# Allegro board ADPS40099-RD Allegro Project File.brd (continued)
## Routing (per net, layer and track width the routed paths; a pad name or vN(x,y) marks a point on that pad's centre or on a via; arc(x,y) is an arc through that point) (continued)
UNNAMED_3_ADMAX77542_I31_SEL2: length 4.9
  BOTTOM w0.254: v3(90.1,19.59) 89.03,19.59 88.77,19.34 88.77,18.67 87.88,17.78 R48.1
UNNAMED_3_ADMAX77542_I31_SEL3: length 5
  BOTTOM w0.254: v3(90.1,20.79) 89.03,20.79 88.77,21.05 88.77,21.59 87.5,22.86 R50.1
UNNAMED_3_ADMAX77542_I31_SEL4: length 6.2
  BOTTOM w0.254: v3(90.5,20.79) 91.57,20.79 91.82,21.05 91.82,21.59 94.49,24.26 R55.1
UNNAMED_3_ADMAX77857_I197_BST1: length 2.7
  TOP w0.229: U3.A3 93.71,45.83 93.22,45.34 C17.2
UNNAMED_3_ADMAX77857_I197_BST2: length 2.7
  TOP w0.229: U3.E3 96.67,45.83 97.16,45.34 C21.1
UNNAMED_3_ADMAX77857_I197_EN1: length 10.2
  TOP w0.229: v3(94.72,45.83) U3.B2
  BOTTOM w0.203: P17.2 88.82,42.06 88.82,43 89.13,43.31 91.06,43.31 92.46,44.7 93.6,44.7 v3(94.72,45.83)
UNNAMED_3_ADMAX77857_I197_IN1: length 4.1
  TOP w0.229: U3.B4 U3.A4 U3.A5 U3.A6
  BOTTOM w0.508: R76.1 86.65,47.31 P35.1
UNNAMED_3_ADMAX77857_I197_LX11: length 11.6
  TOP w0.229: U3.B5 U3.B6 U3.B7 U3.A7 94.32,47.79 v1(93.98,48.13) 93.6,48.51 v1(93.34,48.51) v1(93.34,47.75)
  TOP w0.508: C17.1 v1(89.33,45.34)
  BOTTOM w0.508: v1(93.98,48.13) 93.98,45.97 93.34,45.34 v1(89.33,45.34)
  vias: v1(92.04,53.98) v1(92.04,52.71) v1(92.04,51.44) v1(92.93,53.98) v1(92.93,52.71) v1(92.93,51.44)
UNNAMED_3_ADMAX77857_I197_POKB: length 3.4
  BOTTOM w0.203: v3(95.12,45.43) 95.12,43.3 R27.2
UNNAMED_3_ADMAX77857_I197_SEL: length 3
  TOP w0.229: R77.1 96.69,43.27 95.52,44.43 U3.D1
UNNAMED_3_CN3P_I185_N1: length 2.5
  BOTTOM w0.508: R76.2 88.09,43.87 P17.1
UNNAMED_5_ADLTC3621V2_I158_FB: length 8.2
  TOP w0.203: v1(44.45,9.02) 44.74,9.31 U9.5
  BOTTOM w0.254: v1(44.45,9.02) 44.45,7.96 R92.1
  BOTTOM w0.305: C107.2 46.15,5.8 R102.2 45.81,5.46 R91.1 R92.1
UNNAMED_5_ADLTC3621V2_I158_INTVCC: length 11.6
  TOP w0.254: U9.6 v1(45.39,8.83)
  BOTTOM w0.254: R99.2 47.08,10.67 C106.1 46.39,9.18 46.05,8.83 v1(45.39,8.83)
  BOTTOM w0.381: R99.2 48.39,11.47 48.39,10.79 48.96,10.22 R100.1 51.39,10.22 51.68,10.52 P41.2
UNNAMED_5_ADLTC3621V2_I158_PGOOD: length 5.8
  TOP w0.203: U9.4 44.74,14.58 44.64,14.48 v1(44.06,14.48)
  BOTTOM w0.305: R99.1 48.13,14.1 47.75,14.48 v1(44.06,14.48)
UNNAMED_5_ADLTC3621V2_I158_RUN: length 11.5
  TOP w0.203: v1(44.07,15.88) 44.88,15.88 45.03,15.73 45.07,15.73 45.2,15.59 45.2,15.55 45.39,15.36 U9.3
  BOTTOM w0.381: P39.2 49.56,20.09 45.34,15.88 v1(44.07,15.88)
UNNAMED_5_ADMAX1722X_I186_EN: length 1.7
  TOP w0.356: U10.6 36.21,20.42 R103.2
UNNAMED_5_ADMAX1722X_I186_LX: length 5.1
  TOP w0.356: U10.2 35.56,24.64 35.05,25.15 33.27,25.15 32.77,24.64 L9.2
UNNAMED_5_ADMAX1722X_I186_SEL: length 1.9
  TOP w0.356: U10.4 v1(34.28,21.95)
  BOTTOM w0.356: R45.1 35.5,21.95 v1(34.28,21.95)
UNNAMED_5_ADMAX38889_I125_BKB: length 4.8
  TOP w0.254: U5.4 63.87,17.44 64.41,16.89 64.9,16.89 66.1,15.68 v1(66.1,15.2)
  BOTTOM w0.305: R95.1 v1(66.1,15.2)
UNNAMED_5_ADMAX38889_I125_CAP: length 9.2
  TOP w0.254: U5.2 62.87,17.8 v1(62.87,16)
  TOP w0.381: 69.09,10.88 C73.P 70.07,9.91
  BOTTOM w0.254: v1(66.17,16.89) 66.17,17.53 65.87,17.82 R51.1 63.54,17.82 62.87,17.14 v1(62.87,16)
UNNAMED_5_ADMAX38889_I125_FBCH: length 6.9
  TOP w0.254: v1(63.37,23.62) 63.37,23.62 U5.10
  BOTTOM w0.254: R53.1 v1(63.37,23.62)
  BOTTOM w0.508: R52.2 R53.1 62.35,22.57 C88.1
UNNAMED_5_ADMAX38889_I125_FBCR: length 6.7
  TOP w0.254: v1(66.29,21.84) 64.26,21.84 63.87,21.45 U5.9
  BOTTOM w0.254: R51.2 R52.1 65.83,20.87 66.29,21.34 v1(66.29,21.84)
UNNAMED_5_ADMAX38889_I125_FBS: length 5.6
  TOP w0.254: R71.2 62.61,23.46 62.61,22.1 62.87,21.84 U5.11
  TOP w0.305: R71.2 R72.1
UNNAMED_5_ADMAX38889_I125_ISET: length 2.3
  TOP w0.254: R57.1 61.68,22.14 62.37,21.45 U5.12
UNNAMED_5_ADMAX38889_I125_RDY: length 22.7
  TOP w0.254: U5.3 63.37,17.02 64.39,16
  TOP w0.305: RDY.1 60.33,8.64 60.96,9.27 60.96,12.95 60.41,13.5 v1(59.44,13.5) 59.44,13.97 60.07,14.61 64.01,14.61 64.39,14.99 64.39,16
  BOTTOM w0.305: R97.2 v1(59.44,13.5)
UNNAMED_5_CAP_I104_N1: length 7.5
  TOP w0.508: 57.79,19.05 57.79,17.14 58.88,16.05 v1(60.58,16.05)
  BOTTOM w0.254: R97.1 R96.1
  BOTTOM w0.305: R97.1 v1(60.58,16.05)
UNNAMED_5_CAP_I119_N1: length 3.1
  BOTTOM w0.381: BKB.1 66.04,3.58 ; BKB.1 65,2.54 ; BKB.1 67.08,2.54
UNNAMED_5_NC2P_I157_N1: length 1.4
  BOTTOM w0.305: P38.1 R92.2
UNNAMED_5_NC2P_I163_N1: length 17
  TOP w0.203: 46.23,9.27 46.05,9.45 U9.7
  TOP w0.305: v1(47.5,9.14) 46.36,9.14 46.23,9.27
  BOTTOM w0.305: v1(47.5,9.14) 52.58,9.14 53.21,9.78 53.21,11.48 52.81,11.89 P41.1 49.81,11.89 R100.2 R101.1 51.64,13.22 P42.2
UNNAMED_5_NC2P_I176_N1: length 1.4
  BOTTOM w0.305: R91.2 P28.1
UNNAMED_5_RES_I103_N2: length 1.7
  TOP w0.305: R69.2 54.61,25.78 R98.1
UNNAMED_6_CAP_I13_N2: length 4
  TOP w0.381: 18.8,13.84 18.8,15.14 18.45,15.48 C117.2 18.5,16.17 R117.1
UNNAMED_6_IC24XX32AV2_I1_A0: length 3.4
  TOP w0.305: U14.1 v1(17.53,7.29)
  BOTTOM w0.305: R111.2 17.53,6.69 v1(17.53,7.29) 17.53,7.91 R112.1
UNNAMED_6_IC24XX32AV2_I1_A1: length 3.2
  TOP w0.305: U14.2 v1(18.8,7.29)
  BOTTOM w0.305: R109.2 v1(18.8,7.29) R110.1
UNNAMED_6_IC24XX32AV2_I1_A2: length 3.4
  TOP w0.305: U14.3 v1(20.07,7.29)
  BOTTOM w0.305: R61.2 20.07,6.69 v1(20.07,7.29) 20.07,7.91 R62.1
UNNAMED_6_IC24XX32AV2_I1_SCL: length 2.2
  TOP w0.508: 20.07,13.84 R113.1
UNNAMED_6_IC24XX32AV2_I1_SDA: length 2.3
  TOP w0.508: 21.34,13.84 21.34,15.21 21.59,15.47 R114.1
VCIN: length 10.8
  TOP w0.254: C8.1 35.69,41.02 34.66,39.99 U2.A5
  TOP w0.381: P50.2 39.12,44.2 36.92,42 C8.1
VIO: length 12.2
  TOP w0.508: R4.1 v1(48.01,56.9) ; R13.2 v1(48.01,53.85) ; R3.1 v1(48.01,60.07) ; R14.2 v1(48.01,63.12)
  BOTTOM w0.381: C13.1 42.96,68.83 44.2,68.83 44.45,69.09 U7.5
  BOTTOM w0.508: R19.1 43.05,71.92 v1(43.05,70.99) ; v1(45.85,70.99) 45.85,71.92 R18.1 ; R9.2 v1(39.75,56.26) ; v1(42.08,70.99) C13.1 ; R10.2 v1(39.75,59.31)
VIO1: length 45.5
  TOP w0.254: U2.B1 32.04,38.73 31.72,39.04
  TOP w0.508: P22.2 46.36,40.89 47.37,41.91 47.37,44.83 46.23,45.97 32.41,45.97 v1(30.07,43.64) 30.07,43.63 30.07,42.67 R63.2 29.11,41.69 29.11,40.16 29.73,39.54 C5.1 31.23,39.54 31.72,39.04
  L3_SIG w0.508: v1(30.07,43.64) 34.51,43.64 v1(36.89,41.25)
  BOTTOM w0.508: R25.1 R58.1 36.35,41.79 v1(36.89,41.25)
VIO2: length 23
  TOP w0.254: U2.C1 32.08,38.23 31.78,37.92
  TOP w0.508: 31.78,37.92 30.26,36.41 C6.1 29.38,36.41 29.08,36.12 v1(29.08,33.76) 27.08,31.75 P23.2
  BOTTOM w0.635: v1(29.08,33.76) 29.08,34.42 30.01,35.34 R8.1 R5.1
VIO3: length 11.3
  TOP w0.229: U3.A2 94.1,45.43 92.71,44.04 C86.1
  TOP w0.508: v1(90.93,44.04) C86.1
  L3_SIG w0.381: 86.42,38.23 P17.3 ; P17.3 88.63,38.23 ; P17.3 87.53,39.33 ; P17.3 87.53,37.12
  BOTTOM w0.508: v1(92.84,40.64) R80.1 R27.1 ; R78.1 v1(91.06,40.64)
VIO4: length 37
  TOP w0.508: v1(75.22,60.36) 74.78,60.81 R34.2
  L3_SIG w1.016: v1(75.22,60.36) 77.98,57.61 77.98,54.1 75.22,51.35 75.22,41.82 72.82,39.42 65.48,39.42 P27.2
VIO6: length 80.1
  TOP w0.229: C75.1 86.96,20.39 U6.A6
  TOP w0.508: v1(79.25,19.43) 80.14,20.32 83.31,20.32 83.69,19.94 v1(83.69,19.3) R59.2 86.27,20.95 C75.1
  L4_PWR w0.508: v1(84.84,26.04) 84.84,20.45 v1(83.69,19.3) 85.26,17.74 v1(85.26,15.62) 85.26,12.53 87.38,10.41 93.98,10.41 95.63,12.07 v1(95.63,14.61) 95.63,15.32 97.16,16.84 97.16,21.59 95.63,23.11 v1(95.63,25.4)
  BOTTOM w0.254: R15.2 v1(95.63,14.61)
  BOTTOM w0.381: v1(95.63,25.4) 95,26.04 R85.2 ; R70.2 v1(84.84,26.04) ; R47.2 v1(85.26,15.62)
  BOTTOM w0.508: P29.2 65.79,25.27 66.42,24.64 66.42,22.99 70.48,18.92 78.74,18.92 v1(79.25,19.43) R60.2 ; R59.2 v1(83.69,19.3)
VIO8: length 56
  TOP w0.508: R22.1 R21.1 56.77,44.99
  TOP w0.635: 56.77,44.99 v1(56.77,44.2) 56.77,41.78 54.36,39.37 54.36,37.59 53.31,36.55 P26.2
  BOTTOM w0.508: P36.2 P25.2 62.74,50.01 63.3,49.45 72.06,49.45 72.49,49.02 72.49,41.71 71.86,41.07 60.17,41.07 58.67,42.57 R24.2 57.7,45.05 R28.1 56.77,44.81 v1(56.77,44.2)
VIO9: length 13.7
  TOP w0.508: C117.1 v1(15.77,16.12)
  L3_SIG w1.016: v1(15.77,16.12) 18.55,16.12 22.84,11.83 P47.2
VL: length 6.6
  TOP w0.229: C18.1 95.12,42.58 U3.C1
  TOP w0.508: v1(95.16,41.53) C18.1
  BOTTOM w0.508: P18.2 95.16,38.57 v1(95.16,41.53)
VSYS: length 46.1
  TOP w0.229: 63.02,52.1 U8.G4 U8.F4 ; 63.02,52.1 64.91,52.1 ; 63.02,52.1 63.02,52.37 62.9,52.5 U8.G5 U8.F5 U8.E5
  TOP w0.254: U5.1 62.37,17.16 v1(61.85,16.64)
  L3_SIG w0.508: v1(49.99,70.84) 61.24,70.84 62.74,69.34 62.74,64.36 60.86,62.48 60.86,59 62.43,57.43 62.43,54.13 64.06,52.5 v1(67.31,52.5)
  BOTTOM w0.508: v1(49.99,70.84) 49.99,71.7 49.64,72.05 R29.1
  vias: v1(80.49,49.12) v1(80.49,48.41) v1(80.49,47.7) v1(81.2,49.12) v1(81.2,48.41) v1(81.2,47.7)
W1: length 3.6
  BOTTOM w0.508: TP21.1 109.6,50.04 P14.1

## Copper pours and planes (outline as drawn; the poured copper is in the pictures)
0V9 on TOP: 113.54,25.65 113.54,33.3 113.31,33.53 97.54,33.53 97.28,33.27 97.28,25.65
1V2 on TOP: 74.42,33.02 74.93,33.53 82.8,33.53 83.13,33.2 83.13,25.69 83.05,25.6 74.42,25.6
1V2 on L4_PWR: 74.8,30.48 79.63,30.48 82.55,27.56 82.55,12.19 89.66,5.08 89.66,2.16 89.28,1.78 85.98,1.78 73.66,14.1 73.66,29.31 73.65,29.33
1V8 on TOP: 74.43,11.28 81.14,4.57 81.15,4.57 81.15,3.13 82.63,1.65 83.69,1.65 84.58,2.54 84.58,5.97 83.14,7.42 83.13,7.42 83.13,14.78 74.43,14.78
1V8_VIO on TOP: 57.2,12.27 52.27,12.27 52.08,12.08 48.2,12.08 48.2,8.7 49.4,7.49 57.02,7.49 57.66,8.13 57.66,11.81
1V8_VIO on BOTTOM: 45.61,6.93 45.61,8 45.97,8.37 45.97,8.38 52.83,8.38 54.99,10.54 56.77,10.54 57.28,10.03 57.28,8 56.21,6.93
1V8_VIO on L3_SIG: 51.94,34.85 51.97,34.82 68.71,34.82 69.57,33.96 69.57,31.62 65.01,27.06 60.34,27.06 58.23,24.96 58.23,9.33 55.37,6.48 35.05,6.48 32.89,8.64 32.89,23.88 30.48,26.29 24.38,26.29 23.49,27.18 22.1,27.18 21.46,26.54 21.46,24.64 22.86,23.24 22.86,22.91 22.62,22.67 15.94,22.67 13.59,25.02 13.59,31.5 14.99,32.89 30.35,32.89 39.24,24.13 39.24,12.57 40.39,11.43 46.99,11.43 48.01,12.45 48.01,21.08 43.94,25.15 43.94,33.78 45.01,34.85
3V3 on TOP: 97.55,14.78 106.16,14.78 106.16,5.83 102.23,1.91 98.42,1.91 97.55,2.78
5V0 on TOP: 97.79,49.15 113.16,49.15 113.54,48.77 113.54,42.04 113.16,41.66 102.23,41.66 101.85,42.04 101.85,45.85 101.55,46.15 95.45,46.15 95.44,46.16 95.44,46.21 95.47,46.28 95.75,46.41 95.84,46.63 95.84,47.06 95.86,47.1 95.89,47.11 95.99,47.12 97.03,47.12 97.41,47.5 97.41,48.77
5V0 on BOTTOM: 106.43,46.23 106.68,46.48 106.68,48.9 106.43,49.15 101.22,49.15 101.09,49.02 101.09,47.75 100.84,47.5 97.54,47.5 96.77,46.74 96.77,46.36 96.9,46.23
5V0 on L4_PWR: 74.55,30.99 70.48,26.92 69.72,26.92 69.22,27.43 69.22,28.57 73.66,33.02 86.61,33.02 92.2,38.61 92.2,42.04 99.44,49.28 111.38,49.28 112.52,48.13 112.52,42.8 110.63,40.9 106.31,40.9 103.63,38.23 103.63,34.67 99.95,30.99
5V0_VIO on TOP: 36.14,23.16 39.15,23.16 39.15,23.16 39.42,23.16 39.62,23.37 39.62,27.18 39.12,27.69 36.58,27.69 36.03,27.14 36.03,23.27
5V0_VIO on L4_PWR: 43.94,43.43 43.94,48.26 44.45,48.77 46.48,48.77 46.99,48.26 46.99,38.86 45.47,37.34 45.47,28.96 41.15,24.64 36.83,24.64 36.32,25.15 36.32,27.94 36.83,28.45 40.89,28.45 41.4,28.96 41.4,40.89
12V0 on TOP: 35.1,58.5 34.82,58.5 34.72,58.6 34.72,64.9 34.7,64.92 34.7,65.13 29.21,70.61 29.21,75.44 7.49,75.44 3.17,71.12 3.17,66.67 25.78,66.67 31.24,61.21 31.24,58.04 31.39,57.89 35.05,57.89 35.13,57.96 35.13,58.47
AGND on TOP (solid shape): 30.48,61.34 30.48,56.54 30.12,56.18 30.12,54.18 29.92,53.98 27.81,53.98 27.56,54.23 27.56,61.34 27.81,61.59 30.23,61.59
AGND on TOP (solid shape): 41.53,64.64 41.53,60.58 41.28,60.33 39.5,60.33 39.24,60.58 39.24,64.64 39.37,64.77 41.4,64.77
AGND on TOP: 72.75,38.25 84.68,38.25 84.68,35.46 72.75,35.46
AGND on TOP: 100.02,75.44 113.54,75.44 113.54,49.66 103.38,49.66 103.33,49.71 103.33,54.03 102.36,54.99 95,54.99 94.74,55.25 94.74,56.82 95.41,56.82 96.19,56.82 96.65,57.28 98.02,57.28 98.09,57.35 98.09,59 100.58,59 100.65,58.93 102.98,58.93 103.06,59 103.07,59 103.1,59.03 103.1,59.05 103.23,59.17 103.23,67.97 102.87,68.33 100.2,68.33 99.9,68.63 99.9,69.36 103.12,69.36 103.26,69.42 103.32,69.56 103.32,70.56 103.26,70.7 103.12,70.76 99.9,70.76 99.9,73.36 103.12,73.36 103.26,73.42 103.32,73.56 103.32,74.56 103.26,74.7 103.12,74.76 99.9,74.76 99.9,75.31 ; 8 cut-outs
AGND on TOP: 54.81,57.86 54.81,57.11 57.32,57.11 57.32,57.86
AGND on TOP: 61.47,50.34 61.21,50.6 60.99,50.6 60.86,50.72 60.86,51.36 62.56,51.36 62.66,51.26 62.66,50.47 62.99,50.14 69.39,50.14 69.47,50.06 69.47,48.51 69.34,48.39 63.04,48.39 62.1,47.45 62.1,42.16 61.95,42.01 60.2,42.01 60.05,42.16 60.05,48.26 61.26,48.26 61.47,48.46
AGND on TOP: 53.36,53.5 56.12,53.5 56.21,53.41 56.21,52.17 56.03,51.99 53.19,51.99 52.98,52.2 52.98,53.13
AGND on TOP: 72.52,68.96 69.22,68.96 68.96,69.22 68.96,75.06 69.34,75.44 72.14,75.44 72.52,75.06
AGND on TOP: 0.76,75.44 113.54,75.44 113.54,0.76 0.76,0.76 ; 10 cut-outs
AGND on TOP: 85.09,25.53 87.88,22.73 88.39,22.73 88.9,22.22 88.9,21.46 88.14,21.46 88.14,21.72 88.01,21.84 78.49,21.84 78.11,21.46 78.11,19.05 79.12,18.03 86.23,18.03 86.74,18.54 88.01,18.54 88.14,18.67 88.14,18.92 88.9,18.92 88.9,18.16 88.39,17.65 87.88,17.65 85.09,14.86 85.09,13.21 84.96,13.08 83.69,13.08 83.57,13.21 83.57,15.24 83.31,15.49 74.42,15.49 74.42,24.89 83.31,24.89 83.57,25.15 83.57,27.18 83.69,27.3 84.96,27.3 85.09,27.18
AGND on TOP: 99.57,53.21 102.62,53.21 102.87,52.96 102.87,49.66 97.03,49.66 95.12,47.75 93.22,49.66 87.63,49.66 87.63,52.96 87.88,53.21 90.81,53.21 91.06,52.96 91.06,51.68 92.06,50.67 98.18,50.67 99.31,51.8 99.31,52.96
AGND on TOP: 113.54,1.14 113.16,0.76 105.41,0.76 104.27,1.91 104.27,3.05 106.68,5.46 106.68,24.71 106.86,24.89 113.33,24.89 113.54,24.69
AGND on TOP: 38.48,75.44 59.11,75.44 59.11,69.9 52.53,69.9 51.74,70.69 51.46,70.69 49.71,70.69 49.37,71.03 49.37,74.08 49.32,74.2 49.21,74.28 49.17,74.29 49.17,74.47 49.18,74.48 49.21,74.57 49.23,74.68 48.77,75.13 48.31,74.68 48.32,74.57 48.36,74.48 48.36,74.47 48.36,74.29 48.32,74.28 48.21,74.2 48.17,74.08 48.17,71.03 47.83,70.69 46.79,70.69 46.44,71.03 46.44,74.08 46.4,74.2 46.29,74.28 46.25,74.29 46.25,74.47 46.26,74.48 46.29,74.57 46.3,74.68 45.85,75.13 45.39,74.68 45.4,74.57 45.44,74.48 45.44,74.47 45.44,74.29 45.4,74.28 45.29,74.2 45.25,74.08 45.25,71.87 45,71.63 43.9,71.63 43.65,71.87 43.65,74.08 43.61,74.2 43.5,74.28 43.46,74.29 43.46,74.47 43.46,74.48 43.5,74.57 43.51,74.68 43.05,75.13 42.6,74.68 42.61,74.57 42.64,74.48 42.65,74.47 42.65,74.29 42.61,74.28 42.5,74.2 42.46,74.08 42.46,71.48 42.4,71.39 42.3,71.39 41.87,71.4 41.62,71.04 41.62,70.99 38.86,70.99 37.97,71.88 37.97,74.93
AGND on TOP: 34.8,43.18 36.58,43.18 36.58,44.96 34.8,44.96
AGND on TOP: 61.19,57.89 61.19,60.17 61.34,60.33 63.47,60.33 63.65,60.15 63.65,57.89
AGND on TOP: 97.03,25.15 97.28,24.89 106.17,24.89 106.17,15.49 97.28,15.49 97.03,15.24 97.03,13.21 96.9,13.08 95.63,13.08 95.5,13.21 95.5,14.86 92.71,17.65 92.2,17.65 91.69,18.16 91.69,18.92 92.46,18.92 92.46,18.67 92.58,18.54 99.44,18.54 99.95,19.05 99.95,21.34 99.44,21.84 92.58,21.84 92.46,21.72 92.46,21.46 91.69,21.46 91.69,22.22 92.2,22.73 92.71,22.73 95.5,25.53 95.5,27.18 95.63,27.3 96.9,27.3 97.03,27.18
AGND on TOP: outline of 442 points within 34.16,50.6 77.7,75.44
AGND on TOP: 96.57,59 96.57,57.02 99.34,57.02 99.34,59
AGND on TOP: 93.95,56.69 93.95,55.6 94.08,55.47 95.83,55.47 95.96,55.6 95.96,56.69 95.83,56.82 94.08,56.82
AGND on BOTTOM: 58.17,49.23 58.55,49.23 58.85,48.92 58.85,48.43 58.91,48.29 59.05,48.23 59.59,48.23 59.79,48.03 59.79,46.55 61.32,45.03 61.32,43.25 61.59,42.98 63.97,42.98 64.26,43.27 64.26,46.95 62.56,48.65 62.56,48.92 62.69,49.05 63.28,49.05 63.3,49.05 71.89,49.05 72.08,48.85 72.08,41.88 71.69,41.48 60.34,41.48 59.08,42.74 59.08,44.45 59.17,44.45 59.31,44.51 59.37,44.65 59.37,47.14 59.31,47.29 59.17,47.35 58.4,47.35 58.28,47.47 58.33,47.58 58.34,47.71 58.21,48.03 57.89,48.16 57.56,48.03 57.43,47.71 57.43,47.63 57.35,47.55 57.16,47.55 57.1,47.59 57.02,47.62 56.87,47.78 56.87,47.93 57.05,48.11
AGND on BOTTOM: 45.97,75.44 48.64,75.44 48.64,75.44 113.54,75.44 113.54,0.76 0.76,0.76 0.76,50.47 0.76,50.47 0.76,75.44 40.39,75.44 42.93,75.44 42.93,75.44 45.97,75.44 ; 7 cut-outs
AGND on BOTTOM: 63.25,53.82 63.65,53.82 63.65,50.92 64.3,50.27 72.08,50.27 72.08,49.86 63.47,49.86 63.14,50.18 63.14,50.43 63.22,50.51 63.25,50.61
AGND on BOTTOM: 35.39,59.74 36.89,59.74 36.98,59.67 36.95,59.56 36.8,59.39 36.75,59.18 36.89,58.86 37.21,58.72 37.34,58.74 37.46,58.8 37.49,58.81 37.52,58.79 37.59,58.75 37.66,58.74 38.29,58.74 38.48,58.55 38.48,58.17 38.35,58.04 36.94,58.04 36.81,58.16 36.73,58.22 36.63,58.24 36.35,58.24 36.28,58.26 36.21,58.27 36.01,58.19 35.93,57.98 35.93,57.98 35.9,57.9 35.82,57.87 35.81,57.87 35.61,57.79 35.53,57.59 35.53,57.52 35.56,57.45 35.56,57.28 35.58,57.18 35.63,57.1 35.89,56.84 35.97,56.79 36.07,56.77 36.73,56.77 36.81,56.72 36.81,56.62 36.77,56.51 36.75,56.39 36.8,56.18 36.95,56.01 36.98,55.9 36.89,55.83 35.39,55.83 35.13,56.09 35.13,59.48
AGND on BOTTOM: 96.39,15.37 97.16,15.37 97.28,15.49 97.28,17.27 98.04,18.03 105.79,18.03 106.05,17.78 106.05,16.76 105.92,16.64 105.03,16.64 100.2,11.81 93.73,11.81 93.55,11.99 93.55,13.28 93.73,13.46 95.89,13.46 96.14,13.72 96.14,15.11
AGND on BOTTOM: 102.87,26.67 105.01,26.67 105.08,26.64 105.11,26.56 105.11,26.53 105.11,25.54 105.17,25.4 105.31,25.34 105.79,25.34 105.79,24.26 105.16,24.26 102.87,26.54
AGND on BOTTOM: 43.18,75.39 43.19,75.42 43.23,75.44 45.67,75.44 45.71,75.42 45.72,75.39 45.72,75.14 45.7,75.11 45.69,75.1 45.47,74.94 45.39,74.68 45.4,74.57 45.44,74.48 45.44,74.47 45.44,74.4 45.43,74.36 45.39,74.35 45.35,74.35 45.21,74.29 45.15,74.14 45.15,71.69 44.83,71.37 44.07,71.37 43.75,71.69 43.75,74.14 43.69,74.29 43.55,74.35 43.51,74.35 43.47,74.36 43.46,74.4 43.46,74.47 43.46,74.48 43.5,74.57 43.51,74.68 43.43,74.94 43.19,75.12 43.18,75.15
AGND on BOTTOM: outline of 124 points within 67.18,14.1 113.54,50.16
AGND on BOTTOM: 73.51,75.44 75.79,75.44 75.79,74.88 73.51,74.88
AGND on BOTTOM: 96.52,25.02 97.16,25.02 97.28,24.89 97.28,23.11 98.04,22.35 105.79,22.35 106.05,22.61 106.05,23.62 105.92,23.75 105.03,23.75 100.33,28.45 93.85,28.45 93.55,28.14 93.55,27.1 93.73,26.92 96.14,26.92 96.39,26.67 96.39,25.15
AGND on BOTTOM: 102.23,51.31 99.06,51.31 98.81,51.56 98.81,54.23 98.42,54.61 96.9,54.61 95.76,53.47 95.76,45.72 95.63,45.59 95.5,45.59 94.49,46.61 94.49,53.47 93.34,54.61 92.08,54.61 91.57,54.1 91.57,51.56 91.31,51.31 88.01,51.31 87.88,51.44 87.88,53.21 89.28,54.61 90.68,54.61 91.69,55.63 94.36,55.63 94.74,55.25 96.01,55.25 96.39,55.63 100.33,55.63 102.36,53.59 102.36,51.44
AGND on BOTTOM: 83.31,17.27 82.55,18.03 74.8,18.03 74.55,17.78 74.55,16.76 74.68,16.64 75.56,16.64 80.39,11.81 86.87,11.81 87.05,11.99 87.05,13.26 86.84,13.46 85.98,13.46 83.31,16.13 83.31,17.22
AGND on BOTTOM: 48.9,75.44 56.9,75.44 57.12,75.21 57.12,71.33 57.06,71.24 56.95,71.26 56.26,71.95 54.3,71.95 54.3,72.45 54.25,72.6 54.1,72.66 53.31,72.66 53.17,72.6 53.11,72.45 53.11,71.95 52.6,71.95 52.6,72.45 52.55,72.6 52.4,72.66 51.61,72.66 51.47,72.6 51.41,72.45 51.41,72.37 51.2,72.37 51.19,72.37 51.09,72.4 50.99,72.42 50.68,72.3 50.54,72 50.53,71.95 50.31,71.95 49.93,72.34 49.8,72.42 49.64,72.46 49.47,72.46 49.47,74.14 49.41,74.29 49.26,74.35 49.23,74.35 49.19,74.36 49.17,74.4 49.17,74.47 49.18,74.48 49.21,74.57 49.23,74.68 49.14,74.94 48.92,75.11 48.9,75.12
AGND on BOTTOM: outline of 259 points within 56.44,35.56 113.54,75.44 ; 2 cut-outs
AGND on BOTTOM: 42.29,75.44 49.53,75.44 49.53,74.93 42.29,74.93
AGND on BOTTOM: 82.55,22.35 74.8,22.35 74.55,22.61 74.55,23.62 74.68,23.75 75.56,23.75 80.26,28.45 86.87,28.45 87.05,28.27 87.05,26.97 86.87,26.8 84.84,26.8 84.45,26.42 84.45,24.26
AGND on BOTTOM: 55.25,47.96 55.34,47.96 55.32,47.84 55.32,47.78 55.37,47.56 55.52,47.4 55.52,41.15 53.79,39.42 48.85,39.42 43.99,44.27 43.91,44.33 43.82,44.35 36.55,44.35 36.45,44.33 36.37,44.27 35.74,43.64 35.68,43.56 35.66,43.46 35.66,43.31 35.55,43.31 35.48,43.3 35.42,43.26 35.38,43.25 35.35,43.26 35.29,43.3 35.22,43.31 34.98,43.31 34.98,47.42 38.1,50.55 47.24,50.55 48.77,49.02 48.77,40.92 49.1,40.59 49.18,40.53 49.28,40.51 52.71,40.51 53.98,41.78 53.98,46.99 54.86,47.88 55.17,47.88
AGND on L2_GND, L5_GND: 113.54,75.44 113.54,0.76 0.76,0.76 0.76,75.44 13.46,75.44
AGND on L3_SIG: 0.76,75.44 113.54,75.44 113.54,0.76 0.76,0.76 ; 1 cut-out
AGND on L4_PWR: 0.76,75.44 113.54,75.44 113.54,0.76 0.76,0.76
VBUS on TOP (solid shape): 35.13,57.61 35.13,57.1 35.1,57.07 34.82,57.07 34.72,56.97 34.72,53.26 33.27,51.82 30.76,51.82 30.51,52.07 30.51,55.35 31.24,56.08 31.24,57.53 31.39,57.68 35.05,57.68
VBUS on TOP: 13.34,38.31 13.34,34.29 11.43,32.38 3.17,32.38 2.54,33.02 2.54,33.66 3.17,34.29 10.16,34.29 11.43,35.56 11.43,38.73 10.16,40.01 10.16,41.28 11.43,41.28 12.07,41.91 12.07,43.43 11.68,43.82 10.85,43.82 10.16,43.13 10.16,44.71 10.92,45.47 10.92,47.12 17.3,53.49 29.77,53.49 30.89,54.61 34.52,54.61 34.72,54.41 34.72,53.26 31.68,50.22 20.38,50.22 15.88,45.72 15.88,40.85
VBUS on TOP: 42.99,39.81 42.55,39.37 36.58,39.37 36.32,39.12 35.31,39.12 35.31,39.37 36.66,40.73 39.46,40.73 40.64,41.91 42.67,41.91 42.99,41.59
VBUS on L3_SIG: 20.32,50.16 15.88,45.72 15.88,40.89 14.1,39.12 11.68,39.12 10.16,40.64 8.38,40.64 8.13,40.89 8.13,41.28 6.73,42.67 6.73,44.32 6.98,44.58 10.03,44.58 10.92,45.47 10.92,47.12 17.28,53.47 29.67,53.47 30.23,54.03 30.23,55.37 30.43,55.58 33.53,55.58 33.68,55.42 33.68,51.16 43.26,41.58 43.26,40.21 42.93,39.88 40.39,39.88 30.1,50.16
VCC_EXT on TOP: 30.58,22.2 28.6,22.2 28.45,22.35 28.45,24.89 28.7,25.15 30.48,25.15 30.73,24.89 30.73,22.35
VCC_EXT on TOP: 17.23,25.33 16.57,25.33 16.26,25.02 16.26,22.61 16.64,22.22 17.78,22.22 18.08,22.53 18.08,24.33 17.78,24.64 17.53,24.64 17.23,24.94
VCC_EXT on TOP: 42.32,20.84 42.07,21.09 41.15,21.09 40.89,20.83 40.89,19.31 41.15,19.05 42.08,19.05 42.32,19.29
VCC_EXT on BOTTOM: 40.39,19.05 41.15,19.05 41.4,19.3 41.4,19.3 41.4,20.83 41.15,21.09 34.54,21.09 30.48,25.15 28.7,25.15 28.45,24.89 28.45,22.35 32.51,18.29 39.62,18.29
VCC_EXT on L4_PWR: 18.16,26.04 18.16,28.32 16,30.48 12.95,30.48 12.19,29.72 12.19,28.57 12.83,27.94 14.1,27.94 14.61,27.43 14.61,23.11 16.13,21.59 30.48,21.59 30.99,22.1 30.99,24.64 30.48,25.15 19.05,25.15
VIN_U14 on L3_SIG: 18.29,21.97 23.37,21.97 24.26,22.86 24.26,24.76 24.89,25.4 30.48,25.4 31.5,24.38 31.5,8.13 26.29,2.92 14.61,2.92 13.84,3.68 13.84,14.48 14.61,15.24 16,15.24 16.76,14.48 16.76,7.11 17.4,6.48 20.57,6.48 24.13,10.03 26.54,10.03 27.18,10.67 27.18,19.05 26.54,19.68 18.29,19.68 17.78,20.19 17.78,21.46
BATT on BOTTOM (solid shape): 54.89,59.74 54.89,58.98 52.86,58.98 52.81,59.03 52.81,59.46 53.29,59.94 53.29,60.86 53.77,60.86
BATT on TOP: 89.66,68.07 89.66,62.36 90.42,61.59 92.84,61.59 92.96,61.47 92.96,60.07 92.84,59.94 91.69,59.94 91.52,59.77 91.52,55.65 91.31,55.45 86.79,55.45 86.23,56.01 86.23,67.69 87.12,68.58 89.15,68.58
BATT on TOP: 60.43,52.78 60.43,52.98 60.58,52.98 60.83,53.24 60.83,57.43 61.04,57.63 66.83,57.63 66.93,57.53 66.93,54.25 66.85,54.18 63.09,54.18 61.7,52.78
BATT on BOTTOM: 63.86,58.75 63.86,51 64.39,50.47 83.87,50.47 88.77,55.37 90.42,55.37 92.08,57.02 92.08,61.21 91.69,61.59 88.77,61.59 87.88,62.48 87.88,65.53 88.52,66.17 88.52,68.2 88.27,68.45 87.38,68.45 86.36,67.44 86.36,63.75 82.02,59.41 64.52,59.41
BATT_N on TOP: 73.28,68.96 75.44,68.96 76.84,70.36 76.84,71.37 77.17,71.7 78.87,71.7 79.15,71.98 79.15,75.16 78.87,75.44 73.66,75.44 73.28,75.06
BATT_N on BOTTOM: 77.32,74.27 77.32,64.49 76.71,63.88 70.61,63.88 64.52,69.98 62.53,69.98 62.53,74.27 62.94,74.68 68.25,74.68 68.58,74.35 68.58,72.01 70.23,70.36 72.52,70.36 72.77,70.61 72.77,74.19 73.25,74.68 76.91,74.68
BATT_P on TOP: 28.6,19.71 30.58,19.71 30.73,19.56 30.73,17.02 30.48,16.76 28.7,16.76 28.45,17.02 28.45,19.56
BATT_P on TOP: 100.58,60.45 100.58,62.87 100.84,63.12 102.36,63.12 102.62,62.87 102.62,60.45 102.23,60.07 100.97,60.07
BATT_P on TOP: 42.32,17.78 42.07,18.02 41.15,18.02 40.89,17.77 40.89,16.24 41.15,15.99 42.08,15.99 42.32,16.23
BATT_P on TOP: 77.7,65.53 79.1,65.53 79.25,65.68 79.25,67.67 79.1,67.82 77.67,67.82 77.55,67.69 77.55,65.68
BATT_P on BOTTOM: 31.51,18.02 41.15,18.02 41.39,17.78 41.4,17.78 41.4,16.24 41.15,15.99 28.71,15.99 28.45,16.26 28.45,18.8 28.7,19.05 30.48,19.05
BATT_P on BOTTOM: 100.33,62.87 100.33,60.45 100.71,60.07 102.11,60.07 102.49,60.45 102.49,62.87 102.11,63.25 100.71,63.25
BATT_P on BOTTOM: 61.75,74.68 61.75,69.04 60.27,69.04 58.83,70.48 58.83,74.47 59.03,74.68
BATT_P on L4_PWR: 103.12,74.4 103.12,53.85 91.19,41.91 91.19,38.86 86.11,33.78 73.41,33.78 68.58,28.96 68.58,14.22 66.8,12.45 43.69,12.45 40.39,15.75 40.39,17.27 40.89,17.78 44.45,17.78 46.48,15.75 62.48,15.75 63.5,16.76 63.5,28.96 79.5,44.96 83.31,44.96 86.11,47.75 86.11,59.44 91.19,64.52 91.19,69.98 89.53,71.63 87.38,71.63 81.28,65.53 77.72,65.53 74.42,68.83 66.8,68.83 62.74,64.77 60.2,64.77 59.18,65.79 59.18,73.66 60.96,75.44 102.08,75.44
CHGIN on TOP: 59.44,51.41 59.44,49.1 58.98,48.64 53.62,48.64 53.3,48.96 53.3,50.97 53.75,51.41
CHGIN on L3_SIG: 49.45,61.85 49.45,52.04 52.55,48.95 55.12,48.95 55.42,49.25 55.42,60.91 53.72,62.61 50.22,62.61
LX2 on TOP: 96.52,48.77 97.03,48.77 97.16,48.64 97.16,47.62 96.88,47.35 95.94,47.35 95.92,47.35 95.7,47.25 95.61,47.03 95.61,46.63 95.59,46.6 95.55,46.58 95.49,46.58 95.46,46.6 95.44,46.63 95.44,47.69
LX2 on TOP: 95.52,51 95.52,54.41 98.12,54.41 98.42,54.1 98.42,51.31 98.12,51
LX2 on BOTTOM: 96.01,53.34 97.03,54.36 98.3,54.36 98.42,54.23 98.42,48.9 96.52,46.99 96.01,46.99
PCKP on TOP: 95.55,58.8 95.55,57.25 95.33,57.02 92.58,57.02 92.41,57.2 92.41,58.83 92.58,59 95.35,59
PP_VOUT on TOP (solid shape): 36.32,56.52 37.08,55.75 38.23,55.75 38.48,55.5 38.48,52.07 38.23,51.82 35.18,51.82 34.92,52.07 34.92,56.9 36.32,56.9
PP_VOUT on TOP (solid shape): 38.48,63.5 38.48,60.07 38.23,59.82 37.08,59.82 36.32,59.05 36.32,58.67 34.92,58.67 34.92,63.5 35.18,63.75 38.23,63.75
PP_VOUT on TOP: 42.32,23.89 42.07,24.13 41.15,24.13 40.89,23.88 40.89,22.35 41.15,22.1 42.08,22.1 42.32,22.34
PP_VOUT on TOP: 34.92,62.61 34.92,65.28 29.59,70.61 29.59,75.44 36.96,75.44 37.47,74.93 37.47,71.63 38.61,70.48 51.66,70.48 52.3,69.85 52.3,63.8 51.99,63.5 49.28,63.5 47.5,65.28 38.99,65.28 38.48,64.77 38.48,62.61
PP_VOUT on BOTTOM: 38.35,59.94 38.48,60.07 38.48,68.83 38.1,69.22 33.15,69.22 32.77,68.83 32.77,52.07 33.02,51.82 38.23,51.82 38.48,52.07 38.48,55.5 38.35,55.63 35.31,55.63 34.92,56.01 34.92,59.56 35.31,59.94
PP_VOUT on L4_PWR: 37.21,65.91 34.42,65.91 33.91,65.41 33.91,48.51 40.77,41.66 40.77,29.84 40.39,29.46 36.07,29.46 35.56,28.96 35.56,24.64 36.32,23.88 41.15,23.88 41.4,23.62 41.4,22.61 41.15,22.35 33.78,22.35 33.27,22.86 33.27,30.73 34.8,32.26 36.32,32.26 36.96,32.89 36.96,37.34 26.34,47.96 26.34,64.57 31.5,69.72 37.21,69.72
U6_IN on TOP: 88.9,28.07 88.9,26.04 89.03,25.91 91.57,25.91 91.69,26.04 91.69,28.07 91.57,28.19 89.03,28.19
U6_IN on TOP: 88.9,12.32 88.9,14.35 89.03,14.48 91.57,14.48 91.69,14.35 91.69,12.32 91.57,12.19 89.03,12.19
U6_IN on BOTTOM: 92.71,28.32 87.88,28.32 87.71,28.14 87.71,26.97 87.88,26.8 92.71,26.8 92.89,26.97 92.89,28.14
U6_IN on BOTTOM: 87.88,13.59 92.71,13.59 92.89,13.41 92.89,11.99 92.71,11.81 87.88,11.81 87.71,11.99 87.71,13.41
U6_IN on L4_PWR: 104.39,33.53 104.39,37.34 104.9,37.85 106.81,37.85 107.31,37.34 107.31,29.21 105.28,27.18 95.25,27.18 94.16,26.09 94.16,20.9 95.63,19.43 95.63,17.78 93.73,15.88 93.73,12.95 92.71,11.94 89.28,11.94 88.27,12.95 88.27,29.59 89.15,30.48 101.35,30.48
U9_IN on TOP: 42.55,24 43.31,24.76 51.94,24.76 52.57,24.14 52.57,21.97 52.44,21.84 47.57,21.84 47.19,21.46 47.19,19.49 46.39,18.69 46.39,16.28 46.27,16.17 46.27,14.05 45.82,14.05 45.82,15.8 45.34,16.28 42.65,16.28 42.55,16.38
UNNAMED_2_ADMAX7778X_I78_LX1 on TOP: 66.73,46.84 66.73,43.33 62.48,43.33 62.36,43.46 62.36,46.71 62.48,46.84
UNNAMED_2_ADMAX7778X_I78_LX1 on TOP: 59.99,50.72 59.99,48.59 60.12,48.46 61.14,48.46 61.24,48.56 61.24,50.27 61.11,50.39 60.91,50.39 60.6,50.7 60.6,51.77 60.05,51.77 60.05,50.77
UNNAMED_2_ADMAX7778X_I78_LX1 on BOTTOM: 59.99,50.39 61.32,50.39 62.36,49.35 62.36,48.56 64.06,46.86 64.06,43.36 63.88,43.18 61.67,43.18 61.52,43.33 61.52,45.11 59.99,46.63
UNNAMED_2_CAP_I217_N1 on TOP: 72.75,42.82 72.75,40.54 74.78,40.54 74.78,42.82 74.52,43.08 73,43.08
UNNAMED_2_CAP_I222_N1 on TOP: 76.05,42.82 76.05,40.54 78.08,40.54 78.08,42.82 77.83,43.08 76.3,43.08
UNNAMED_2_CAP_I224_N1 on TOP: 82.65,42.82 82.65,40.54 84.68,40.54 84.68,42.82 84.43,43.08 82.91,43.08
UNNAMED_2_CAP_I227_N1 on TOP: 79.35,42.82 79.35,40.54 81.38,40.54 81.38,42.82 81.13,43.08 79.6,43.08
UNNAMED_2_CAP_I232_N2 on TOP: 93.47,61.34 93.73,61.59 95.12,61.59 95.38,61.34 95.38,60.07 95.12,59.82 93.73,59.82 93.47,60.07
UNNAMED_2_CAP_I235_N2 on TOP: 91.92,56.69 91.92,55.6 92.05,55.47 93.42,55.47 93.55,55.6 93.55,56.69 93.42,56.82 92.05,56.82
UNNAMED_2_MODUSB24P4PSHLD_I13_SH1 on TOP: 0.76,38.66 9.27,38.66 9.27,36.25 0.76,36.25
UNNAMED_2_MODUSB24P4PSHLD_I13_SH1 on TOP: 0.76,49.96 9.27,49.96 9.27,45.77 0.76,45.77
UNNAMED_2_MODUSB24P4PSHLD_I13_SH1 on BOTTOM: 0.76,49.96 9.27,49.96 9.27,45.77 6.22,45.77 6.22,38.66 9.27,38.66 9.27,36.25 0.76,36.25
UNNAMED_2_RES_I185_N1 on TOP: 93.29,75.44 99.39,75.44 99.7,75.13 99.7,60.58 98.93,59.82 96.14,59.82 95.89,60.07 95.89,61.34 96.14,61.59 97.41,61.59 97.66,61.85 97.66,70.61 96.9,71.37 96.22,71.37 93.32,71.37 93.09,71.6 93.09,75.23
UNNAMED_2_RES_I234_N1 on TOP: 90.98,70.99 90.98,69.08 91.35,68.71 96.01,68.71 96.32,69.01 96.32,70.99 96.14,71.17 91.16,71.17
UNNAMED_2_RES_I264_N2 on TOP: 91.32,63.96 90.34,63.96 90.04,64.26 90.04,66.42 90.57,66.94 90.57,67.93 91.45,67.93 91.61,67.77 91.61,66.34 91.32,66.04
UNNAMED_2_TRANNMOSFETV15_I187_D1 on TOP: 93.67,65.69 93.67,63.32 93.67,63.32 95.34,63.32 95.34,65.69
UNNAMED_3_ADMAX77542_I19_BST1 on TOP: 90.55,6.6 90.55,9.02 91.57,9.02 91.57,6.6
UNNAMED_3_ADMAX77542_I19_BST2 on TOP: 89.03,6.6 89.03,9.02 90.04,9.02 90.04,6.6
UNNAMED_3_ADMAX77542_I19_BST3 on TOP: 89.03,33.78 89.03,31.37 90.04,31.37 90.04,33.78
UNNAMED_3_ADMAX77542_I19_BST4 on TOP: 90.55,33.78 90.55,31.37 91.57,31.37 91.57,33.78
UNNAMED_3_ADMAX77542_I19_IN11 on TOP: 91.57,15.49 90.55,15.49 90.42,15.62 90.42,17.65 91.69,16.38 91.69,15.62
UNNAMED_3_ADMAX77542_I19_IN11 on L2_GND: 90.42,17.53 90.42,15.62 90.55,15.49 91.57,15.49 91.69,15.62 91.69,16.38 90.55,17.53
UNNAMED_3_ADMAX77542_I19_IN21 on TOP: 89.03,15.49 90.04,15.49 90.17,15.62 90.17,17.65 88.9,16.38 88.9,15.62
UNNAMED_3_ADMAX77542_I19_IN21 on L2_GND: 90.04,17.53 88.9,16.38 88.9,15.62 89.03,15.49 90.04,15.49 90.17,15.62 90.17,17.53
UNNAMED_3_ADMAX77542_I19_IN31 on TOP: 89.03,24.89 90.04,24.89 90.17,24.76 90.17,22.73 88.9,24 88.9,24.76
UNNAMED_3_ADMAX77542_I19_IN31 on L2_GND: 90.04,22.86 88.9,24 88.9,24.76 89.03,24.89 90.04,24.89 90.17,24.76 90.17,22.86
UNNAMED_3_ADMAX77542_I19_IN41 on TOP: 91.57,24.89 90.55,24.89 90.42,24.76 90.42,22.73 91.69,24 91.69,24.76
UNNAMED_3_ADMAX77542_I19_IN41 on L2_GND: 90.42,22.86 90.42,24.76 90.55,24.89 91.57,24.89 91.69,24.76 91.69,24 90.55,22.86
UNNAMED_3_ADMAX77542_I19_LX11 on TOP: 90.81,17.65 92.08,16.38 92.08,10.92 91.82,10.67 90.55,10.67 90.55,9.78 91.82,9.78 92.08,9.53 92.08,8 95.25,8 95.25,14.73 92.58,17.4 92.08,17.4 91.44,18.03 90.81,18.03
UNNAMED_3_ADMAX77542_I19_LX11 on L2_GND: 90.81,18.03 91.44,18.03 92.08,17.4 92.58,17.4 95.25,14.73 95.25,8 92.08,8 92.08,16.38 90.81,17.65
UNNAMED_3_ADMAX77542_I19_LX21 on TOP: 89.79,17.65 88.52,16.38 88.52,10.92 88.77,10.67 90.04,10.67 90.04,9.78 88.77,9.78 88.52,9.53 88.52,8 85.34,8 85.34,14.73 88.01,17.4 88.52,17.4 89.15,18.03 89.79,18.03
UNNAMED_3_ADMAX77542_I19_LX21 on L2_GND: 89.79,18.03 89.15,18.03 88.52,17.4 88.01,17.4 85.34,14.73 85.34,8 88.52,8 88.52,16.38 89.79,17.65
UNNAMED_3_ADMAX77542_I19_LX31 on TOP: 89.79,22.73 88.52,24 88.52,29.46 88.77,29.72 90.04,29.72 90.04,30.61 88.77,30.61 88.52,30.86 88.52,32.38 85.34,32.38 85.34,25.65 88.01,22.99 88.52,22.99 89.15,22.35 89.79,22.35
UNNAMED_3_ADMAX77542_I19_LX31 on L2_GND: 89.79,22.35 89.15,22.35 88.52,22.99 88.01,22.99 85.34,25.65 85.34,32.38 88.52,32.38 88.52,24 89.79,22.73
UNNAMED_3_ADMAX77542_I19_LX41 on TOP: 90.81,22.73 92.08,24 92.08,29.46 91.82,29.72 90.55,29.72 90.55,30.61 91.82,30.61 92.08,30.86 92.08,32.38 95.25,32.38 95.25,25.65 92.58,22.99 92.08,22.99 91.44,22.35 90.81,22.35
UNNAMED_3_ADMAX77542_I19_LX41 on L2_GND: 90.81,22.35 91.44,22.35 92.08,22.99 92.58,22.99 95.25,25.65 95.25,32.38 92.08,32.38 92.08,24 90.81,22.73
UNNAMED_3_ADMAX77857_I197_BST1 on TOP: 93.85,45.85 91.44,45.85 91.44,44.83 92.84,44.83
UNNAMED_3_ADMAX77857_I197_BST2 on TOP: 96.39,45.85 98.81,45.85 98.81,44.83 97.41,44.83
UNNAMED_3_ADMAX77857_I197_IN1 on TOP: 92.46,49.15 84.81,49.15 84.81,45.52 85.14,45.19 88.52,45.19 89.48,46.15 94.79,46.15 94.8,46.16 94.8,46.21 94.78,46.28 94.49,46.41 94.41,46.63 94.41,47.06 94.39,47.1 94.35,47.11 94.26,47.12 93.22,47.12 92.84,47.5 92.84,48.77
UNNAMED_3_ADMAX77857_I197_IN1 on L3_SIG: 84.35,47.4 86.49,47.4 87.66,48.56 87.66,56.49 87.64,56.5 87.64,59.32 86.26,60.71 86.26,66.42 90.86,71.02 90.86,73.96 90.37,74.45 87.6,74.45 82.58,69.42 82.58,49.17
UNNAMED_3_ADMAX77857_I197_LX11 on TOP: 94.74,47.37 94.74,47.75 93.73,48.77 93.22,48.77 93.09,48.64 93.09,47.62 93.34,47.37
UNNAMED_3_ADMAX77857_I197_LX11 on TOP: 94.72,54.41 94.72,51 92.13,51 91.69,51.44 91.69,54.1 92,54.41
UNNAMED_3_ADMAX77857_I197_LX11 on BOTTOM: 94.23,53.34 93.22,54.36 92.08,54.36 91.82,54.1 91.82,48.9 93.73,46.99 94.23,46.99
UNNAMED_5_ADLTC3621V2_I158_SW on TOP: 46.47,15.61 46.47,14.05 47.17,14.05 48.15,13.07 52.31,13.07 52.58,13.34 52.58,15.62 52.32,15.88 46.74,15.88
UNNAMED_5_ADMAX38889_I125_CAP on TOP: 71.75,11.18 71.75,18.41 71.2,18.97 65.96,18.97 65.69,18.7 64.26,18.7 64.17,18.62 64.17,18.25 65.91,16.51 67.95,16.51 68.58,15.88 68.58,9.65 76.58,1.65 77.98,1.65 78.49,2.16 78.49,4.45
UNNAMED_5_ADMAX38889_I125_LX1 on TOP: 64.18,18.9 65.38,18.9 66.39,19.9 68.57,19.9 68.71,20.04 68.71,20.83 68.2,21.34 65.39,21.34 64.18,20.12
UNNAMED_5_CAP_I104_N1 on TOP: 62.06,20.12 62.06,19.49 61.97,19.4 59.18,19.4 58.05,18.27 56.02,18.27 55.7,18.59 55.7,27.76 57.4,29.46 58.93,29.46 59.44,28.96 59.44,27.94 58.17,26.67 58.17,25.86 59.01,25.02 60.24,25.02 60.38,24.88 60.38,23.89 60.24,23.75 59.08,23.75 58.85,23.52 58.85,20.59 59.23,20.21 61.97,20.21
UNNAMED_5_CAP_I119_N1 on BOTTOM: 61.73,14.02 65.68,14.02 66.04,13.66 66.04,6.98 67.31,5.71 67.31,2.16 66.8,1.65 65.02,1.65 64.52,2.16 64.52,4.06 61.61,6.97 61.61,13.89
UNNAMED_5_CN2P_I181_N1 on TOP: 35.05,21.08 35.38,21.41 35.38,22.46 35.49,22.56 35.63,22.56 35.74,22.46 35.74,20.79 35.63,20.69 35.63,19.63 35.51,19.51 35.51,17.48 35.05,17.02 31.5,17.02 30.99,17.53 30.99,19.56 30.63,19.91 25.93,19.91 25.84,20 25.84,21.78 26.06,22 31.4,22 31.86,22.46 33.67,22.46 33.67,21.45 34.04,21.08
VIO on L4_PWR: 38.48,74.04 38.86,74.42 40.41,74.42 41.48,73.36 48.26,73.36 49.53,72.09 49.53,54.86 48.26,53.59 44.96,53.59 43.43,52.07 43.43,47.24 42.67,46.48 40.41,46.48 38.48,48.41
VIO3 on L3_SIG: 83.06,42.55 88.14,42.55 89.92,44.32 91.06,44.32 91.69,43.69 91.69,42.29 93.73,40.26 97.16,40.26 98.68,38.73 98.68,36.83 96.37,34.52 70.46,34.52 69.27,35.71 67.97,35.71 67.49,36.2 67.49,37.47 67.97,37.95 78.46,37.95
VIO8 on TOP: 53.1,43.89 56.84,43.89 57.15,44.2 57.15,45.72 56.57,46.3 53.16,46.3 52.58,45.72 52.58,44.41
VSYS on TOP: 84.45,49.61 84.45,43.38 69.24,43.38 69.24,48.03 69.7,48.49 69.7,50.57 69.47,50.8 66.93,50.8 66.93,51.77 66.7,51.99 60.45,51.99 60.45,52.6 61.8,52.6 63.17,53.98 67.06,53.98 67.28,54.2 67.28,57.56 68.3,58.57 76.99,58.57 77.9,59.49 77.9,63.86 79.63,65.58 79.63,75.16 79.91,75.44 85.78,75.44 85.98,75.23 85.98,51.13
VSYS on L4_PWR: 54.74,22.99 61.34,16.38 62.1,16.38 62.23,16.51 62.23,28.45 79.25,45.47 83.06,45.47 83.95,46.36 83.95,49.35 83.39,49.91 76.2,49.91 64.39,38.1 61.47,38.1 58.93,35.56 50.04,35.56 46.99,32.51 46.99,28.96 42.16,24.13 42.16,22.61 41.4,21.84 36.83,21.84 34.29,19.3 25.91,19.3 25.4,18.8 25.4,16 25.91,15.49 37.85,15.49 40.64,18.29 43.18,18.29 44.96,20.07 44.96,24.64 45.97,25.65 54.36,25.65 54.74,25.27

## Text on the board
Ref Des/Silkscreen Bottom: 08-081852 REV C Z | SECONDARY SIDE
User.Comments: -P30 (PIN 1 AND 2) | -P35 (PIN 1 AND 2) | -P22 (PIN 1 AND 2) | -P12 (PIN 1 AND 2) | -P39 (PIN 1 AND 2) | -P40 (PIN 1 AND 2) | -P10 (PIN 1 AND 2) | -P47 (PIN 2 AND 3) | -P50 (PIN 1 AND 2) | -P29 (PIN 1 AND 2) | -P27 (PIN 1 AND 2) | -P20 (PIN 1 AND 2) | -P28 (PIN 1 AND 2) | -P41 (PIN 1 AND 2) | -P16 (PIN 1 AND 2) | -P21 (PIN 1 AND 2) | -P26 (PIN 1 AND 2) | -P13 (PIN 1 AND 2) | -P17 (PIN 1 AND 2) | -P18 (PIN 1 AND 2) | -P19 (PIN 1 AND 2) | -P11 (PIN 1 AND 2) | -P3 (PIN 1 AND 2) | -P4 (PIN 1 AND 2) | 5.    SOLDER SHORT PIN 1 AND PIN 2 OF THE FOLLOWING: | 4.    INSTALL M029337 (MFG_PN: QPC02SXGN-RC) ON BELOW COMPONENT PINS
Ref Des/Silkscreen Top: PRIMARY SIDE | 08-081852 REV C Z | A1 | EEPROM | I2C | CONTROLLER | USB-C PD | BATTERY MANAGEMENT SYSTEM | ADPS40099-RD | PRIORITIZER | POWER SOURCE | VIO SUPPLY | BATTERY | BACKUP | 1S BATTERY | CHARGER | FUEL GAUGE + | PROTECTOR + | AUTHENTICATOR | BUCK-BOOST | CONVERTER | MULTI-PHASE BUCK | A
PAGE_OUTLINE: TEST PROCESS | N/A | C | AS PER ECR-129430 | 10MAR26 | R. EUSTACIO | BATTERY MANAGEMENT SYSTEM
BODY_CENTER: FAB NOTES REVISION: 2ND NOVEMBER 2022 | 8.   IMPEDANCE REQUIREMENTS: IF NO STACKUP IS DEFINED, THE VENDOR IS ALLOWED TO ADJUST THE DIELECTRIC | 13.  PLATING SPECIFICATION: | 1.   DIMENSIONS ARE IN INCHES (EXCEPT WHERE NOTED). | ALL DOCUMENTS & SPECIFICATIONS REFERRED TO BELOW SHOULD BE THE LATEST REVISIONS. | 2.  BOARD MATERIAL:(USE CHECKED ITEMS) | 3.   ALL LAMINATES & BONDING MATERIALS SHOULD BE SELECTED FROM IPC-4101 OR IPC-4103,(TG>170 DEGC TD>300 DEGC) | 4.   REFER TO IPC-6010 SERIES, CLASS 2 FOR FABRICATION. | 5.   REFER TO LAMINATION DIAGRAM FOR OVERALL BOARD THICKNESS, TOLERANCE APPLIES AFTER ALL LAMINATION AND PLATING | 6.   BOW & TWIST NOT TO EXCEED 0.0075 INCHES (0.75%) PER LINEAR INCH AND SHOULD BE MEASURED PER IPC-TM-650, METHOD 2.4.22. | 7.   ACCEPTABILITY PER ADI SPECIFICATION TST00115. | 9.   FILLET OPTIONS TO ENHANCE RELIABILITY AT PAD JUNCTIONS WHERE SPACING PERMITS. | 10.  THIEVING: | 11.  LAYER TO LAYER REGISTRATION SHALL BE WITHIN 0.003 INCHES. | 12.  DRILL SIZES ARE FINISHED HOLE SIZES. ALL HOLES SHALL BE LOCATED WITHIN 0.005 INCHES DTP,UNLESS SPECIFIED. | 14.  SURFACE FINISH: | 15.  SOLDERMASK: | 16.  APPLY SILKSCREEN TO BOTH SIDES USING A NON-CONDUCTIVE, EPOXY BASED INK PER ARTWORK. | (X) WHITE | ( ) OTHER | PROCESSES. FINISHED THICKNESS MEASURED FROM TOP COPPER TO BOTTOM COPPER. | (X)  ISOLA 370HR OR S1000-2 OR IT180 OR EQUIVALENT | ( )  ISOLA-FR408HR OR EQUIVALENT | ( )  ISOLA IS410 | ( )  MEGTRON 6 | ( )  NELCO-4000-13 | ( )  ROGERS 4350B | ( ) ROGERS 3003 | ( ) ARLON 85N | ( ) EM370D | ( )  OTHER ________________________ | ( ) FILLETS ALLOWED | (X) FILLETS NOT ALLOWED | ( ) VENDOR MAY ADD THIEVING TO COMPENSATE FOR LOW COPPER DENSITY AREAS MAINTAINING A MINIMUM | ( ) VENDOR MAY NOT ADD THIEVING TO COMPENSATE FOR LOW COPPER DENSITY AREAS. | (X) LPI | ( ) OTHER_________ | COLOR | (X) GREEN | HINDER PROPER SOLDER WICKING. BARREL RELIEF ON SOLDERMASK ALLOWED IN UNFILLED VIA IN PAD HOLES. | (X) REFER TO LAMINATION DIAGRAM FOR FINISHED COPPER WEIGHT/THICKNESS REQUIRMENTS | (X) IMMERSION GOLD (ENIG) 1.58-3.94 MICRO INCHES OVER 118-236 MICRO INCHES MIN. OF ELECTROLESS NICKEL PER IPC-4552 | ( ) OSP (ORGANIC SOLDERABILITY PRESERVATIVE) | ( ) IMMERSION SILVER | ( ) SOFT WIRE BONDABLE GOLD 30-50 MICRO INCHES OF SOFT WIRE | ( ) EDGE CONNECTOR FINGERS ARE TO BE PLATED WITH 100 MICRO-INCHES(.0001") OF LOW STRESS | THICKNESS & TRACE WIDTHS TO MEET THE IMPEDANCE REQUIREMENT. IF SPECIFIED, THE VENDOR MUST | TRACE WIDTH & SPACING THAT IMPACT THE REQUIREMENTS MUST HAVE WRITTEN APPROVAL FROM ADI. | MINIMUM BARREL PLATING OF 0.001 INCHES. PLATED HOLES SHALL NOT BE ROUGH OR IRREGULAR SO AS TO | SOLDERMASK OVER BARE COPPER OR BARE GOLD (BOTH SIDES) TO MEET IPC-SM-840. | IF PRESENT,DO NOT MODIFY SOLDERMASK DEFINED PADS (MASK OPENINGS LESS THAN COPPER PAD) WITHOUT APPROVAL. | MEET THE REQUIREMENTS LISTED IN THE IMPEDANCE TABLE. ANY ADJUSTMENT MADE TO THE DEFINED STACKUP, | UL FLAMMABILITY RATING 94V-0. BOARD MATERIAL & CONSTRUCTION SHALL MEET THE REQUIREMENTS OF UL796/UL796F. | BONDABLE GOLD OVER 100-150 MICRO INCHES OF NICKEL | NICKEL UNDER 30 MICRO-INCHES (.0003') OF GOLD | 0.100 INCH CLEARANCE FROM ALL COPPER FEATURES, | THE STARTING COPPER WEIGHT/THICKNESS CAN VARY AS LONG AS THE FINISHED COPPER | WEIGHT/THICKNESS IS NOT LESS THAN THE SPECIFIED VALUE. | UNLESS OTHERWISE SPECIFIED | HOMOGENOUS MATERIALS IN THIS BOARD SHALL BE COMPLAINT WITH THE EU DIRECTIVE 2002/95/EC | WORKMANSHIP SHALL CONFORM TO IPC-A-600, CLASS 2. | 21.  INTENTIONAL SHORTS: | 26. BOARDS TO BE SHIPPED SINGULATED AFTER FABRICATION PROCESS | 17.  FINAL ELECTRICAL TEST TO BE PERFORMED USING PROVIDED IPC-D-356A NETLIST OR ODB++ FORMAT FILE. | 22.  PEMNUTS: | 23.  MANUFACTURER TO ETCH/STAMP WITH PERMANENT NON-CONDUCTIVE INK | ON SECONDARY SIDE UNLESS OTHERWISE SPECIFIED: | 18.  A TIME DOMAIN REFLECTOMETER REPORT (TDR) FOR EACH IMPEDANCE CONTROLLED LAYER & A CERTIFICATE | 19.  IF PRESENT, ALL BLIND/BURIED VIAS WITH AN ASPECT RATIO <1:1 TO BE PLATED SHUT WITH COPPER WHEN | 20.  FOR VIA FILL INFORMATION REFER TO DRILL CHART: | 24.  MINIMUM DESIGN LINE WIDTH IS .0040 INCH. | 25.  MINIMUM DESIGN LINE SPACING IS .0040 INCH. | SMOOTHEN EDGES AND FREE FROM BURRS AFTER DEPANELIZATION PROCESS | IS ACCEPTABLE, ALL OTHER INSTANCES MUST BE REPORTED. | IF AN INTENTIONAL SHORT REPORT IS SUPPLIED AND DOES NOT MATCH THE FAB DATA THEN | THE PCB SHALL HAVE A VERIFICATION STAMP. | (X)  NON-CONDUCTIVE EPOXY FILL ALL 0.0050 AND 0.0101 INCHES DRILLED VIAS | ( )  COPPER FILL ALL 0.XXXX INCHES DRILLED VIAS | ( ) PEMNUTS TO BE INSTALLED BY FABRICATOR | ( ) PEMNUTS NOT TO BE INSTALLED BY FABRICATOR | ( ) NOT APPLICABLE | USED AS VIA-IN-PAD OR AS A STACKED VIA. BLIND/BURIED VIAS WITH AN ASPECT RATIO >1:1 TO BE FILLED | A. UL CODE-FLAMMABILITY RATING FOR THOSE APPROVED MATERIALS(IF APPLICABLE) | B. DATE CODE | C. LOT NUMBER | D. MANUFACTURER LOGO | CAN'T BE PERFORMED BECAUSE THE TRACE LENGTH IS TOO SHORT ON THE OUTER LAYERS AT THE PIN ESCAPES | ADI APPROVAL IS REQUIRED. | OF COMPLIANCE SHALL BE PROVIDED BY VENDOR AT TIME OF SHIPMENT. INSTANCES WHERE TDR TESTING | WITH NON-CONDUCTIVE EPOXY. | REFERENCE PLANE | L5_GND | L2_GND | NOTES: | TOOLING: | FINISH: | MATERIAL: | TESTING: | MISCELLANEOUS:
DIMENSION: LABEL PLACEMENT INFORMATION | HALF SIZE LABELS ARE | AVAILABLE IN THE LIBRARY | PLACE WHEELIE BIN LOGO | TO SUIT THE LAYOUT. | PLACE ROHS COMPLIANT LOGO | TO SUIT THE LAYOUT OR | DELETE IF NOT REQ'D. | PLACE CHINA ROHS COMPLIANT | LOGO TO SUIT THE LAYOUT OR | 1.THE BOARD SIZE CAN BE ADJUSTED TO SUIT THE APPLICATION. | 2.THE MOUNTING HOLES CAN BE MOVED/REMOVED TO SUIT THE APPLICATION. | 3.THE FIDUCIALS CAN BE MOVED TO SUIT THE APPLICATION. | 4.ADJUST THE DIMENSIONS TO SUIT THE APPLICATION. | 5.ADD THE CORRECT LAYER STACKUP ON FAB2 BASED ON THE NO OF LAYERS ON THE PCB. | 6.THE ROHS COMPLIANT AND WHEELIE BIN LOGO'S CAN BE MOVED TO THE DESIRED LOCATION. | HALF SIZE VERSIONS OF THE LABELS ARE AVAILABLE IN THE LIBRARY. | NOTES FOR TEMPLATE USAGE. | REF | GENERIC D-SIZE TEMPLATE BR-067706A
User.11: P1
User.16: DIA MAX/SEE NOTE 20 | 2
User.22: L2 GND | 08-      -07
User.23: L3 SIG | 08-      -08
User.24: L4 PWR | 08-      -09
User.25: L5 GND | 08-      -10
User.45: 44.0x20.0 | 37.0x26.0 | +2MILS/-0 | DIA MAX/SEE NOTE 20 | FIGURE | SIZE | 5.0 | 5.01 | 10.0 | 10.1 | 35.0 | 40.0 | 45.0 | 50.0 | 26.0 | 67.0 | 75.0 | 125.0 | PLATED | NON-PLATED | DRILL CHART: TOP to BOTTOM | DRILL CHART: TOP to L2_GND | ALL UNITS ARE IN MILS | QTY | 167 | 51 | 885 | 17 | 2 | 65 | 58 | 1 | 4 | 1092 | TOLERANCE/NOTES | TOTAL HOLES:
